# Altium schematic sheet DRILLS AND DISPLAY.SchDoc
size A4; DocumentNumber: 5; SheetNumber: 5; SheetTotal: 6; PageSetup: Record=PageOptions|CenterHorizontal=True|CenterVertical=True|PrintScale=0.97|XCorrection=1.00|YCorrection=1.00|PrintKind=0|BorderSize=5000000|LeftOffset=5|BottomOffset=0|Orientation=1|PaperLength=1000|PaperWidth=1000|Scale=100|PaperSource=7|PrintQuality=-4|MediaType=1|DitherType=10|PaperKind=A4|PrintScaleMode=1
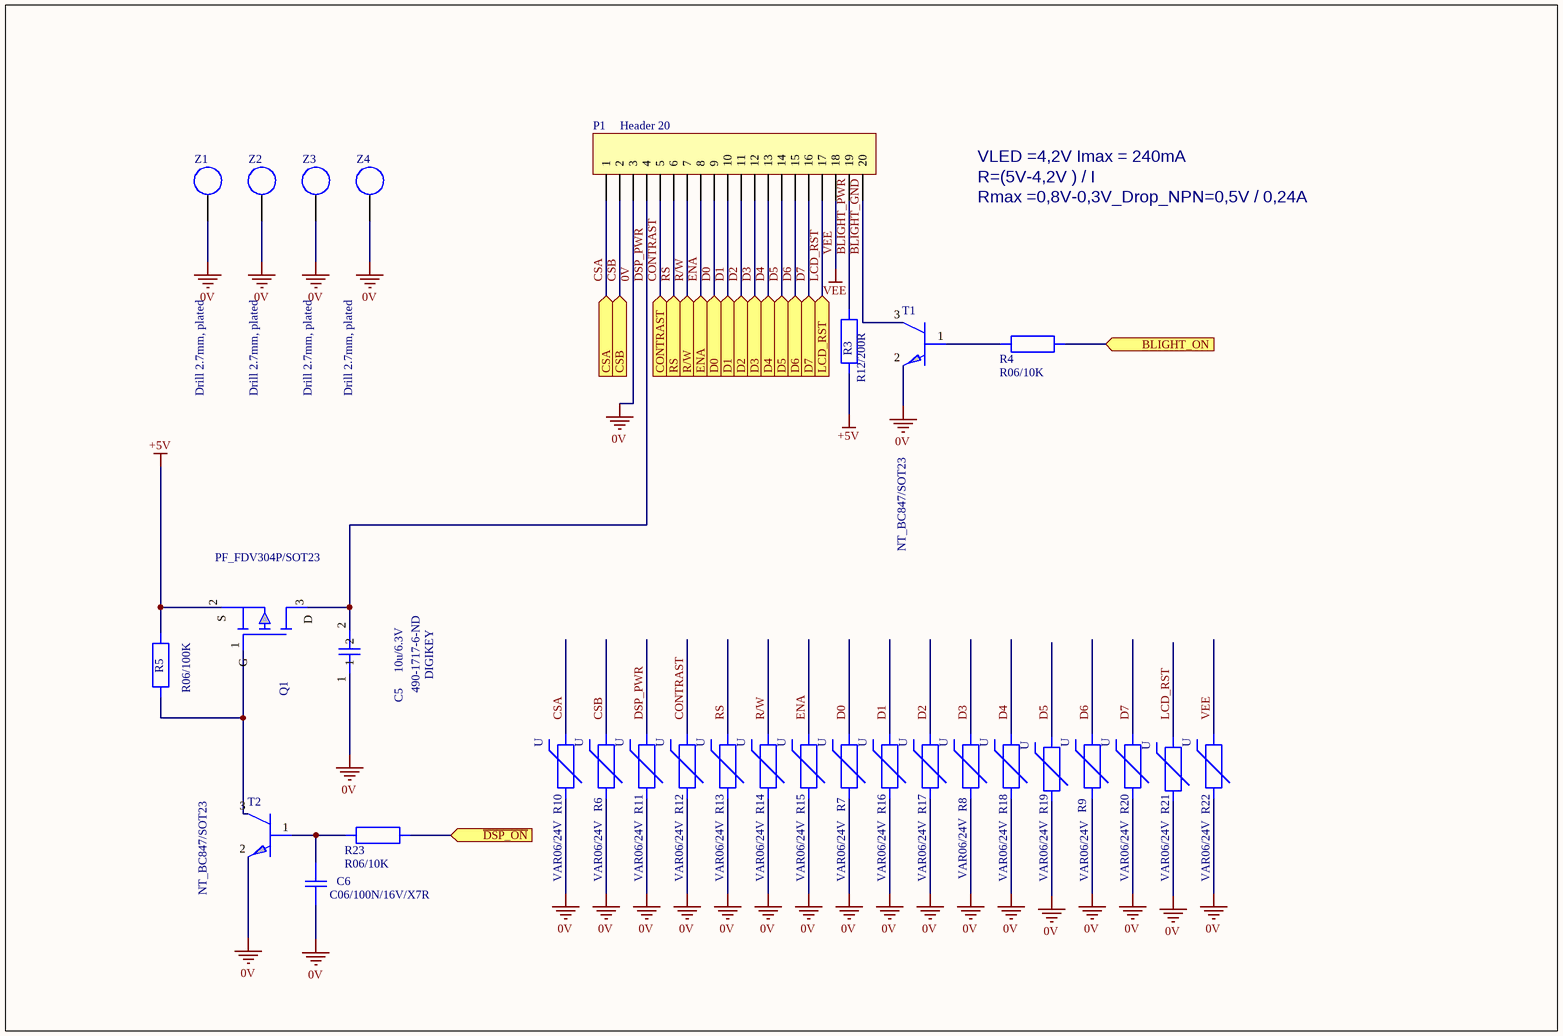
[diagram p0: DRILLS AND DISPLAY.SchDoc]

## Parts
C5  value 10u/6.3V  Supplier 1: DIGIKEY  Supplier Part Number 1: 490-1717-6-ND  [C02X75Y0A1]  (hidden comment: C08/10U)
C6  C06/100N/16V/X7R  [C02X60Y0A1]
P1  Header 20  [HDR1X20]
Q1  PF_FDV304P/SOT23  [TR03X80Y95A0]
R3  R12/200R  [R02X125Y0A0]
R4  R06/10K  [R02X60Y0A0]
R5  R06/100K  [R02X60Y0A0]
R6  VAR06/24V  [R02X60Y0A0]
R7  VAR06/24V  [R02X60Y0A0]
R8  VAR06/24V  [R02X60Y0A0]
R9  VAR06/24V  [R02X60Y0A0]
R10  VAR06/24V  [R02X60Y0A0]
R11  VAR06/24V  [R02X60Y0A0]
R12  VAR06/24V  [R02X60Y0A0]
R13  VAR06/24V  [R02X60Y0A0]
R14  VAR06/24V  [R02X60Y0A0]
R15  VAR06/24V  [R02X60Y0A0]
R16  VAR06/24V  [R02X60Y0A0]
R17  VAR06/24V  [R02X60Y0A0]
R18  VAR06/24V  [R02X60Y0A0]
R19  VAR06/24V  [R02X60Y0A0]
R20  VAR06/24V  [R02X60Y0A0]
R21  VAR06/24V  [R02X60Y0A0]
R22  VAR06/24V  [R02X60Y0A0]
R23  R06/10K  [R02X60Y0A0]
T1  NT_BC847/SOT23  [TR03X80Y95A0]
T2  NT_BC847/SOT23  [TR03X80Y95A0]
Z1  Drill 2.7mm, plated  [Drill 2.7mm]  (no BOM)
Z2  Drill 2.7mm, plated  [Drill 2.7mm]  (no BOM)
Z3  Drill 2.7mm, plated  [Drill 2.7mm]  (no BOM)
Z4  Drill 2.7mm, plated  [Drill 2.7mm]  (no BOM)

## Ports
BLIGHT_ON (in), CONTRAST (in), CSA (in), CSB (in), D0 (in), D1 (in), D2 (in), D3 (in), D4 (in), D5 (in), D6 (in), D7 (in), ENA (in), LCD_RST (in), R/W (in), RS (in), ~{DSP_ON} (in)

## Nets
0V: C5.1 C6.1 P1.3 R6.1 R7.1 R8.1 R9.1 R10.1 R11.1 R12.1 R13.1 R14.1 R15.1 R16.1 R17.1 R18.1 R19.1 R20.1 R21.1 R22.1 T1.2(E) T2.2(E) Z1.1 Z2.1 Z3.1 Z4.1
+5V: Q1.2(S) R3.1 R5.2
VEE: P1.18 R22.2
~{DSP_ON}: R23.1 ; port ~{DSP_ON}
BLIGHT_GND: P1.20 T1.3(C)
BLIGHT_ON: R4.1 ; port BLIGHT_ON
BLIGHT_PWR: P1.19 R3.2
CONTRAST: P1.5 R12.2 ; port CONTRAST
CSA: P1.1 R10.2 ; port CSA
CSB: P1.2 R6.2 ; port CSB
D0: P1.9 R7.2 ; port D0
D1: P1.10 R16.2 ; port D1
D2: P1.11 R17.2 ; port D2
D3: P1.12 R8.2 ; port D3
D4: P1.13 R18.2 ; port D4
D5: P1.14 R19.2 ; port D5
D6: P1.15 R9.2 ; port D6
D7: P1.16 R20.2 ; port D7
DSP_PWR: C5.2 P1.4 Q1.3(D) R11.2
ENA: P1.8 R15.2 ; port ENA
LCD_RST: P1.17 R21.2 ; port LCD_RST
R/W: P1.7 R14.2 ; port R/W
RS: P1.6 R13.2 ; port RS
NetC6_2: C6.2 R23.2 T2.1(B)
NetQ1_1: Q1.1(G) R5.1 T2.3(C)
NetR4_2: R4.2 T1.1(B)

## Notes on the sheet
- VLED =4,2V Imax = 240mA
- R=(5V-4,2V ) / I
- Rmax =0,8V-0,3V_Drop_NPN=0,5V / 0,24A

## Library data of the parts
C5 = C08/10U/6V3/X5R: CHIP CAP 0805  10U 6V3 X5R; Geometry.Height: 0.99mm; TYPE: GRM21BR60J106KE19L; MFG.#1: MURATA
C6 = C06/100N/16V/X7R: CHIP-CAP. 0603 16V X7R; Manufacturer Part Number 1: C0603..; VALUE: 100n; MFG.#1: KEMET; Geometry.Height: 1.00 mm; SUPP.#1: BUERKLIN; SUPP.ART.#1: 53 D 2068
P1 = Header 20: Header, 20-Pin; Manufacturer Part Number 1: 613 020 111 21; Geometry.Height: 9.0mm; MFG.#1: WUERTH; VALUE: 20 PINS
Q1 = PF_FDV304P/SOT23: P-CH MOSFET 0A46 2V7G 0W35; VALUE: 25V/0R87; MFG.#1: FAIRCHILD; Geometry.Height: 1.12mm; SUPP.#1: FARNELL; SUPP.ART.#1: 995-850
R3 = R12/200R: MINI-MELF 1% 1/4W; Manufacturer Part Number 1: MMA 0204-50 1%; VALUE: 200R; MFG.#1: BEYSCHLAG; Geometry.Height: 0.45mm; SUPP.#1: BUERKLIN; SUPP.ART.#1: 06 E 596
R4 R23 = R06/10K: CHIP RESISTOR 10K OHM 0.063W 1% 0603 SMD; Manufacturer Part Number 1: MC 0.063W 0603 1% 10K; MFG.#1: MULTICOMP; Geometry.Height: 0.45mm; SUPP.#1: FARNELL; SUPP.ART.#1: 9330399
R5 = R06/100K: CHIP RESISTOR 100K OHM 0.063W 1% 0603 SMD; Manufacturer Part Number 1: MC 0.063W 0603 1% 100K; MFG.#1: MULTICOMP; Geometry.Height: 0.45mm; SUPP.#1: FARNELL; SUPP.ART.#1: 9330402
R6-R22 = VAR06/24V: CHIP VARISTOR 24V  0603 SMD; Manufacturer Part Number 1: 0603ESDA-TR1; MFG.#1: BUSSMANN; Geometry.Height: 0.6mm; SUPP.#1: FARNELL; SUPP.ART.#1: 1470613
T1 T2 = NT_BC847/SOT23: TRANSISTOR NPN SOT23; Manufacturer Part Number 1: BC847B; VALUE: 45V/0A1; MFG.#1: SIEMENS; Geometry.Height: 1.09mm; SUPP.#1: BUERKLIN; SUPP.ART.#1: 12 S 6268
Z1-Z4 = DRILL_2.7mm: Geometry.Height: 2.5mm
